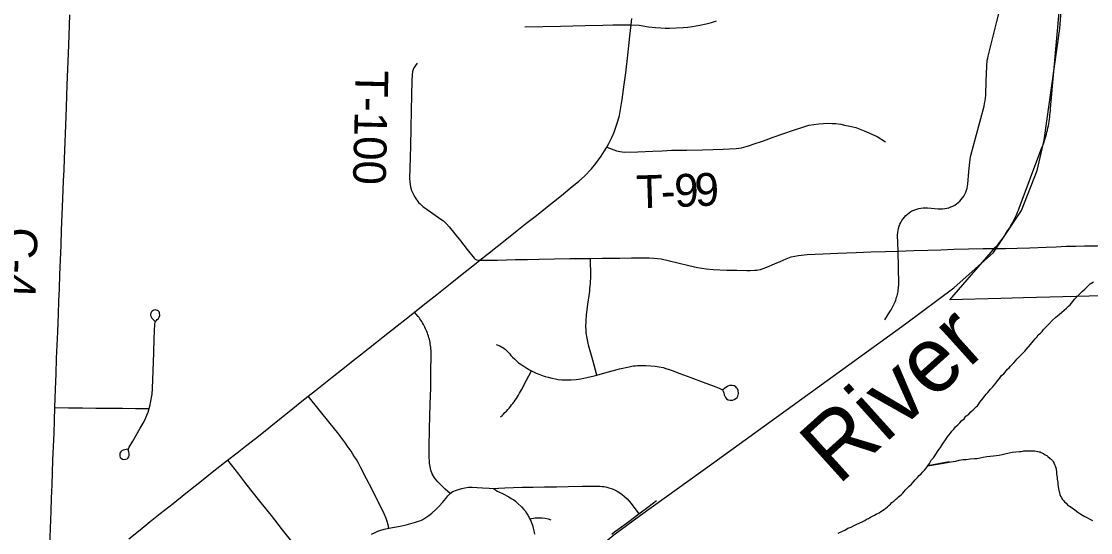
# Model space of a CAD drawing. Extents: x 103424 to 290657, y 38711 to 110967.
# Drawn here: x 133964 to 143819, y 91660 to 96372 of the extents above; entities that cross this region are included whole.
import ezdxf

# ---------------------------------------------------------------- set-up
doc = ezdxf.new("R2010")
doc.units = 0
for name, color, linetype in [('GM_X_Corporation', 7, 'Continuous'), ('GM_X_County_Road', 7, 'Continuous'), ('GM_X_County_Road_Text', 7, 'Continuous'), ('GM_X_Major_River', 7, 'Continuous'), ('GM_X_Major_River_Text', 7, 'Continuous'), ('GM_X_Minor_River', 7, 'Continuous'), ('GM_X_Rail_Line', 7, 'Continuous'), ('GM_X_Township_Road', 7, 'Continuous'), ('GM_X_Township_Road_Text', 7, 'Continuous')]:
    doc.layers.add(name, color=color, linetype=linetype)

msp = doc.modelspace()

# ---------------------------------------------------------------- linework, layer by layer
at = {"layer": 'GM_X_Corporation'}
msp.add_lwpolyline([(145135.5, 93872.2), (143199.9, 93823.5), (142990.7, 93818.2), (142521.7, 93806.3), (142943.1, 94290.2), (142970.1, 94321), (143003.1, 94365.9), (143020.5, 94390.6), (143037.3, 94415.7), (143053.7, 94441), (143069.6, 94466.6), (143085.2, 94492.5), (143100.3, 94518.6), (143114.7, 94545), (143129.5, 94576.7), (143137.6, 94595.2), (143145.4, 94613.8), (143152.7, 94632.5), (143159.8, 94651.4), (143361.2, 95186.5), (143373.3, 95216.1), (143380.4, 95234.9), (143387.2, 95253.9), (143393.5, 95273.1), (143399.5, 95292.3), (143405.3, 95311.6), (143410.9, 95331), (143415.9, 95350.5), (143420.7, 95370.2), (143425, 95389.8), (143429, 95409.6), (143432.8, 95429.4), (143436.1, 95449.3), (143439.1, 95469.2), (143441.9, 95489.2), (143444.2, 95509.2), (143446.2, 95529.3), (143447.7, 95549.4), (143449, 95569.5), (143589.8, 97142.1)], dxfattribs=at)
at = {"layer": 'GM_X_County_Road'}
for points in [[(134227.3, 91538.2), (134232.5, 91698.2), (134237.8, 91858.1), (134242.5, 91979.1), (134247.3, 92100), (134250.8, 92213.9), (134254.2, 92327.8), (134259.6, 92452.6), (134265.1, 92577.3), (134269.1, 92694.8), (134273.1, 92812.3), (134276.6, 92897.5), (134280.2, 92982.6), (134284.8, 93124), (134289.3, 93265.3), (134294.1, 93388.4), (134298.9, 93511.5), (134305.2, 93676.5), (134309.6, 93792.3), (134314.1, 93908.2), (134319.2, 94039.8), (134324.4, 94171.3), (134329.9, 94309.2), (134335.3, 94447), (134340.7, 94592.5), (134346.1, 94737.9), (134352.9, 94902.9), (134357.1, 95003.3), (134361.3, 95103.8), (134367.4, 95259.9), (134373.4, 95415.9), (134379, 95580.9), (134382.5, 95684.6), (134386, 95788.3), (134392.1, 95932), (134398.1, 96075.7), (134404.5, 96240.7), (134408.3, 96337), (134412, 96433.4)], [(134953.5, 91602.2), (135058.2, 91686.8), (135150.9, 91761.8), (135243.7, 91836.9), (135361.7, 91930.2), (135479.6, 92023.5), (135608.9, 92126.2), (135673.6, 92177.6), (135738.3, 92229), (135863.7, 92328.3), (135951.5, 92395), (136031, 92458.5), (136120.8, 92529.1), (136210.6, 92599.6), (136297.8, 92669.7), (136385, 92739.8), (136467.1, 92805.7), (136549.2, 92871.5), (136607.3, 92916.9), (136675.8, 92969.3), (136751.7, 93031.3), (136827.6, 93093.3), (136957.4, 93195.2), (137022.9, 93246.6), (137088.3, 93298), (137162.2, 93356.9), (137236, 93415.8), (137297.1, 93463.6), (137426.9, 93565.6), (137499.1, 93622.3), (137571.3, 93679), (137588.3, 93692.6), (137683, 93767.8), (137793.9, 93856), (137915.2, 93954.1), (138043.3, 94055.7), (138141.3, 94132.4), (138189.7, 94170.4), (138259.8, 94227.5), (138349.5, 94298.3), (138439.3, 94369), (138533.2, 94443.2), (138627.1, 94517.5), (138710.5, 94584.1), (138794, 94650.7), (138868.2, 94709.3), (138942.5, 94767.9), (139022.2, 94833.9), (139101.9, 94899.9), (139153.9, 94946.9), (139217.8, 95011.9), (139259.9, 95062.3), (139308.4, 95129.9), (139340, 95178.4), (139360.7, 95213.8), (139378.1, 95245.1), (139405.5, 95300.9), (139426.4, 95351.1), (139446.3, 95404.8), (139461.9, 95453), (139475.8, 95505.3), (139487.3, 95561.1), (139502, 95652.6), (139520.4, 95789.3), (139534.8, 95897.6), (139552.3, 96059.2), (139561.6, 96146.8), (139570.8, 96234.3), (139583.4, 96340.6), (139590.7, 96398.8)]]:
    msp.add_lwpolyline(points, dxfattribs=at)
at = {"layer": 'GM_X_Major_River'}
for points in [[(142128.7, 92068.5), (142142.6, 92084.9), (142166.4, 92107.6), (142182.2, 92126.1), (142202, 92146.6), (142221.8, 92167.2), (142239.6, 92185.7), (142255.5, 92202.2), (142271.3, 92220.6), (142287.2, 92237.1), (142303, 92255.5), (142318.7, 92276), (142334.5, 92298.5), (142350.1, 92327.1), (142371.9, 92349.7), (142383.7, 92368.1), (142393.5, 92384.4), (142405.3, 92402.8), (142415.1, 92417.2), (142424.9, 92433.5), (142434.8, 92445.8), (142444.6, 92460.1), (142454.4, 92474.4), (142487.8, 92523.5), (142499.6, 92541.9), (142513.4, 92558.3), (142527.2, 92576.8), (142541, 92595.2), (142556.8, 92613.7), (142574.6, 92634.2), (142594.4, 92654.8), (142612.3, 92673.3), (142632.1, 92693.8), (142652, 92710.3), (142669.7, 92734.9), (142695.6, 92751.5), (142713.4, 92772.1), (142735.3, 92790.6), (142751.1, 92807.1), (142765, 92819.5), (142774.9, 92829.7), (142788.7, 92848.2), (142798.5, 92862.5), (142812.3, 92880.9), (142830.1, 92901.4), (142843.9, 92919.9), (142857.7, 92938.3), (142871.6, 92950.7), (142883.4, 92967.1), (142897.3, 92981.4), (142913.1, 92999.9), (142928.9, 93020.4), (142944.7, 93038.9), (142960.5, 93059.4), (142978.2, 93081.9), (142997.9, 93108.5), (143017.8, 93125), (143031.7, 93139.4), (143041.6, 93151.7), (143053.4, 93166.1), (143067.3, 93180.5), (143081.2, 93192.9), (143095, 93209.3), (143110.8, 93225.7), (143126.7, 93242.2), (143142.5, 93260.6), (143160.3, 93279.1), (143182.1, 93301.8), (143198, 93318.2), (143213.9, 93332.6), (143223.7, 93346.9), (143265.2, 93394.2), (143277, 93410.5), (143290.8, 93429), (143306.7, 93445.4), (143322.5, 93461.9), (143336.2, 93484.3), (143356.2, 93498.8), (143372, 93515.3), (143385.8, 93531.7), (143407.6, 93556.3), (143435.3, 93585.1), (143465.1, 93613.9), (143496.8, 93644.8), (143528.6, 93671.7), (143552.5, 93692.3), (143576.3, 93710.9), (143596.2, 93729.4), (143616.1, 93746), (143629.9, 93760.3), (143641.8, 93774.7), (143653.6, 93791.1), (143669.4, 93811.6), (143687.2, 93830.1), (143705.1, 93846.6), (143722.9, 93865.1), (143742.7, 93885.6), (143764.6, 93904.2), (143788.4, 93926.8), (143814.1, 93953.6), (143846.1, 93972.3)], [(141490.5, 91655), (141504.5, 91661.3), (141518.5, 91667.6), (141532.5, 91673.9), (141546.5, 91680.3), (141560.5, 91686.6), (141580.4, 91701.1), (141612.5, 91711.7), (141634.5, 91724.3), (141658.5, 91734.8), (141720.6, 91764.2), (141738.6, 91772.6), (141754.5, 91783), (141770.5, 91791.4), (141790.5, 91803.8), (141808.5, 91812.2), (141826.5, 91822.7), (141842.5, 91829), (141854.4, 91837.3), (141868.5, 91843.6), (141884.4, 91854), (141900.4, 91864.4), (141916.3, 91874.8), (141930.2, 91887.2), (141946.2, 91897.6), (141960.1, 91909.9), (141974, 91922.3), (141985.8, 91936.7), (142005.8, 91951.2), (142021.6, 91965.6), (142035.5, 91978), (142049.4, 91990.3), (142061.4, 92000.7), (142075.3, 92013), (142087.2, 92025.4), (142101, 92039.7), (142112.9, 92054.1), (142128.7, 92068.5)]]:
    msp.add_lwpolyline(points, dxfattribs=at)
at = {"layer": 'GM_X_Minor_River'}
msp.add_lwpolyline([(142515.8, 92311.9), (142318.7, 92276), (142534, 92312.2), (142552.1, 92314.6), (142576.3, 92319), (142608.4, 92327.7), (142644.6, 92334.4), (142672.8, 92334.9), (142690.9, 92337.3), (142709.1, 92339.6), (142747.3, 92342.3), (142771.5, 92344.8), (142799.7, 92349.3), (142829.8, 92355.9), (142862, 92360.5), (142894.3, 92365.2), (142924.5, 92367.7), (142948.6, 92370.2), (142974.8, 92374.7), (143003, 92379.2), (143027.1, 92385.7), (143067.3, 92394.5), (143095.4, 92401.1), (143163.9, 92406.4), (143180, 92408.7), (143194.1, 92411), (143204.1, 92413.2), (143218.2, 92413.4), (143234.4, 92413.7), (143250.5, 92414), (143262.6, 92414.2), (143276.8, 92414.5), (143286.8, 92414.6), (143305, 92412.9), (143317.2, 92411.1), (143331.3, 92409.4), (143343.5, 92405.6), (143353.6, 92403.7), (143363.8, 92397.8), (143374, 92394), (143384.2, 92388.1), (143400.5, 92378.3), (143414.8, 92370.5), (143425, 92362.6), (143443.4, 92346.7), (143457.8, 92334.9), (143466, 92324.9), (143474.3, 92313), (143482.7, 92296.9), (143486.9, 92286.9), (143491.1, 92274.9), (143497.5, 92258.8), (143499.7, 92248.7), (143501.9, 92238.7), (143504.2, 92222.6), (143504.4, 92210.4), (143504.6, 92198.3), (143506.9, 92182.2), (143509.2, 92168.1), (143511.5, 92154), (143513.8, 92137.9), (143516.1, 92121.8), (143516.4, 92105.6), (143518.8, 92085.4), (143523.2, 92063.3), (143536.2, 92011), (143542.6, 91995), (143550.9, 91983), (143557.2, 91968.9), (143567.5, 91957), (143577.8, 91945.1), (143592.1, 91931.2), (143606.5, 91917.3), (143624.9, 91903.5), (143647.4, 91887.7), (143671.9, 91870), (143700.5, 91850.3), (143729.1, 91830.6), (143765.8, 91809), (143790.3, 91797.4), (143810.7, 91785.6), (143835.1, 91771.9)], dxfattribs=at)
at = {"layer": 'GM_X_Rail_Line'}
msp.add_lwpolyline([(133875.3, 84761), (134206.1, 85023.5), (134695.7, 85421.3), (135168.4, 85804.7), (135472.6, 86146.8), (135770.9, 86563.5), (136107.4, 87051.7), (138204.8, 90053), (139003.6, 91176.8), (139218.1, 91468.2), (139423.2, 91640.3), (139671.2, 91822), (140345.3, 92305.3), (142112.2, 93585.6), (142557.7, 93916.9), (142922.5, 94241.9), (143182.7, 94627.5), (143325.5, 94997.6), (143391, 95277.5), (143535.3, 96306.5), (143604.3, 97220.4), (143676.2, 97697.4)], dxfattribs=at)
at = {"layer": 'GM_X_Township_Road'}
for points in [[(139583.4, 96340.6), (139657.8, 96335.5), (139742.6, 96322.7), (139809.2, 96316.8), (139856.6, 96312.3), (139897.5, 96308.8), (139938, 96309.5), (140062.7, 96314.4), (140105.7, 96317.5), (140149.7, 96325.1), (140216.5, 96336.9), (140274.4, 96349), (140323.6, 96362.9), (140371.4, 96377)], [(142044.2, 94255.3), (142040.3, 94406.1), (142041.3, 94425.8), (142043.9, 94445.4), (142047.9, 94464.6), (142053.7, 94483.6), (142060.7, 94501.9), (142069, 94519.7), (142078.9, 94536.8), (142090.2, 94553.1), (142102.5, 94568.4), (142116.2, 94582.7), (142130.8, 94595.9), (142146.4, 94607.9), (142162.7, 94618.7), (142180.1, 94628.2), (142198.3, 94636.2), (142216.6, 94642.8), (142235.8, 94648), (142255.1, 94651.6), (142274.8, 94653.7), (142294.4, 94654.3), (142314.1, 94653.3), (142414.5, 94644.5), (142434.1, 94643.5), (142454, 94644.1), (142473.6, 94646.2), (142493, 94649.9), (142512.2, 94655.1), (142530.8, 94661.7), (142548.7, 94669.8), (142566.1, 94679.3), (142582.7, 94690.1), (142598.3, 94702.2), (142612.9, 94715.5), (142626.5, 94729.9), (142638.8, 94745.3), (142649.9, 94761.6), (142659.7, 94778.8), (142668.3, 94796.6), (142675.4, 94815.1), (142680.9, 94834.1), (142685, 94853.4), (142687.5, 94873), (142697.6, 94987.7), (142707.7, 95102.4), (142710.5, 95119.8), (142714.5, 95136.9), (142757.4, 95296.3), (142796.7, 95442.7), (142836.1, 95589.1), (142842.2, 95614.1), (142846.7, 95639.4), (142849.7, 95664.9), (142851.5, 95690.5), (142856.2, 95823.8), (142861, 95957.2), (142862.2, 95976.9), (142864, 95995), (142866.5, 96013.8), (142870.1, 96032.5), (142874.4, 96051), (142914.4, 96211.1), (142954.5, 96371.2), (142978, 96465.1)], [(138604.1, 96322.2), (138769.1, 96325.6), (138934.1, 96329), (139046.8, 96331.3), (139159.5, 96333.6), (139324.6, 96337.2), (139414.1, 96339.1), (139503.6, 96341), (139583.4, 96340.6)], [(137612.4, 95986), (137597.2, 95966.7), (137579.7, 95938.7), (137570.3, 95909.8), (137566.7, 95880.6), (137563.8, 95827.3), (137560.9, 95690.3), (137558, 95553.2), (137554, 95388.6), (137550, 95224), (137547.1, 95119.9), (137544.2, 95015.8), (137541.7, 94928.1), (137543.4, 94888.9), (137546.3, 94867.4), (137550.5, 94847.3), (137560.3, 94814.8), (137568.4, 94794), (137580.1, 94769.7), (137592.1, 94747.9), (137602.1, 94733), (137611.6, 94720.9), (137625.5, 94704.1), (137638.8, 94690.1), (137651.8, 94676.8), (137666.1, 94663.8), (137681.7, 94652.1), (137756.5, 94601), (137831.4, 94550), (137855.4, 94532.9), (137873.4, 94514.8), (137882.7, 94504.8), (137908, 94478.4), (138010.5, 94349), (138073.6, 94269.3), (138136.8, 94189.6), (138147.4, 94181.3), (138159.4, 94174.8), (138189.7, 94170.4)], [(139360.7, 95213.8), (139448.9, 95179.2), (139480.4, 95171.9), (139522.7, 95168.1), (139646, 95168.8), (139783.2, 95175.7), (139869.6, 95179.9), (139956, 95184.1), (140098.4, 95186.5), (140240.8, 95188.9), (140336, 95191.7), (140431.3, 95194.5), (140490.5, 95197.6), (140551.8, 95200.7), (140600, 95206.6), (140643.3, 95218), (140675.5, 95227.4), (140708.8, 95239.1), (140804, 95272), (140893.2, 95304), (140982.3, 95335.9), (141088.2, 95371.7), (141165.3, 95397.8), (141222.8, 95414.4), (141267.2, 95421), (141314.6, 95427.2), (141357.6, 95432.1), (141389.4, 95433.8), (141435.9, 95431.8), (141470.5, 95430.4), (141516.2, 95423.4), (141550.5, 95416.8), (141599.4, 95406.8), (141653.4, 95393.3), (141701.2, 95376.7), (141731.6, 95364.3), (141776, 95346.2), (141808.6, 95329.9), (141829.7, 95320.9), (141850.2, 95309.5), (141928.8, 95261)], [(142937.2, 94278.7), (143035.5, 94279.6), (143141.8, 94281.8), (143257.9, 94284.9), (143409, 94291.2), (143501.3, 94295.1), (143593.5, 94298.9), (143678.2, 94300.6), (143762.9, 94302.2), (143880.3, 94304.4), (143994.1, 94307.9), (144114.2, 94313.2), (144191.7, 94317.2), (144289.1, 94319), (144385.3, 94317.7), (144501.8, 94317.2), (144628.4, 94320.3), (144718.6, 94323.3), (144808.9, 94326.3), (144968.7, 94331.4), (145107.3, 94337.6), (145201.2, 94340.9), (145295, 94344.2)], [(138189.7, 94170.4), (138255.3, 94172), (138353.4, 94170.6), (138435.9, 94173.3), (138518.4, 94175.9), (138627.6, 94178.5), (138736.9, 94181.1), (138877.9, 94183.8), (139018.9, 94186.4), (139114.1, 94186.9), (139209.4, 94187.3), (139316, 94188.8), (139478.9, 94191.1), (139586.3, 94191.5), (139679.9, 94193.6), (139749.2, 94192.7), (139792.8, 94190.2), (139859.5, 94182.2), (140015.2, 94148.2), (140114.7, 94122.7), (140197, 94104.2), (140276.3, 94090.3), (140341.3, 94085.7), (140467.2, 94079.4), (140558.8, 94077.9), (140650.3, 94076.4), (140682.5, 94077), (140724.5, 94078.6), (140742.1, 94079.4), (140757.7, 94081.9), (140774.9, 94086.1), (140801.3, 94093.9), (140833.6, 94105.9), (140906.2, 94136.1), (140956.6, 94159.2), (141013.7, 94183.9), (141060.3, 94202.8), (141125.7, 94215.8), (141205.9, 94224.6), (141353.2, 94230.1), (141487.9, 94236.8), (141573.4, 94239.8), (141658.8, 94242.7), (141793.8, 94247.5), (141928.8, 94252.3), (142044.2, 94255.3), (142116.2, 94257.7), (142188.5, 94260.7), (142318.5, 94263.7), (142438.9, 94267.5), (142559.4, 94271.4), (142693.5, 94275), (142827.8, 94278.7), (142937.2, 94278.7)], [(141923.6, 93622.9), (141972.7, 93700.5), (141980, 93712.5), (141987.1, 93724.8), (141993.9, 93737.2), (142000.2, 93749.8), (142006.3, 93762.7), (142011.8, 93775.6), (142017.1, 93788.8), (142022.1, 93802), (142026.7, 93815.4), (142030.7, 93828.9), (142034.5, 93842.6), (142038, 93856.3), (142040.8, 93870.1), (142043.6, 93884), (142045.8, 93898), (142047.6, 93912.1), (142048.9, 93926.1), (142050.1, 93940.2), (142050.7, 93954.4), (142047.5, 94104.9), (142044.2, 94255.3)], [(139268.4, 93112.2), (139230.2, 93250.7), (139191.9, 93389.3), (139187.7, 93405.1), (139183.9, 93421), (139180.6, 93437), (139177.6, 93453.1), (139174.9, 93469.2), (139172.6, 93485.4), (139170.9, 93501.6), (139169.3, 93517.9), (139168.1, 93534.2), (139167.4, 93550.5), (139168.4, 93615.8), (139169.4, 93632.1), (139171.2, 93648.4), (139172.9, 93664.7), (139186.2, 93764.5), (139199.5, 93864.3), (139202.3, 93887), (139204.8, 93909.7), (139207, 93932.4), (139208.8, 93955.2), (139210.1, 93978.1), (139211.1, 94000.9), (139211.9, 94023.7), (139209.4, 94187.3)], [(135140.7, 92803.5), (135150.6, 92838.8), (135154.6, 92855.1), (135158.2, 92871.4), (135161.2, 92887.8), (135164, 92904.3), (135166.5, 92920.8), (135168.5, 92937.4), (135170, 92954), (135171.3, 92970.7), (135172.1, 92987.3), (135178.3, 93152.3), (135184.5, 93317.2), (135189.6, 93450.5), (135194.6, 93583.8), (135196.9, 93596.9), (135203.2, 93609), (135208.5, 93616), (135216.6, 93623.4), (135228.4, 93635.2), (135235.5, 93646.6), (135240.4, 93661.2), (135238.2, 93686.1), (135234.4, 93694.1), (135227.4, 93702.3), (135218.9, 93707.6), (135206.9, 93711.4), (135196.4, 93712.6), (135185.7, 93711.2), (135177.6, 93707.9), (135169.5, 93702.3), (135162.4, 93694.2), (135157, 93682.5), (135154.7, 93672.7), (135155.5, 93661.8), (135159.6, 93648.9), (135166, 93637.2), (135175.6, 93626.4), (135196.8, 93605.9)], [(137915.1, 92021.3), (137870.8, 92061.1), (137802.8, 92129.1), (137770.5, 92164.7), (137749.2, 92201.4), (137736.8, 92237), (137731, 92270.7), (137725.9, 92296.3), (137722.8, 92377.9), (137722.3, 92392.6), (137723.9, 92485), (137725.5, 92577.4), (137727.1, 92619.1), (137729.7, 92731.3), (137732.2, 92843.5), (137737.5, 92994.1), (137739.1, 93144.8), (137740.6, 93295.5), (137739.7, 93339.9), (137738.7, 93354.7), (137737.4, 93369.4), (137735.4, 93384.1), (137733.1, 93398.8), (137730.6, 93413.3), (137727.6, 93427.9), (137724.1, 93442.3), (137720.3, 93456.6), (137716.3, 93470.8), (137711.8, 93484.9), (137706.8, 93498.9), (137701.5, 93512.7), (137696, 93526.4), (137689.9, 93539.9), (137683.4, 93553.3), (137676.9, 93566.5), (137669.6, 93579.5), (137662.3, 93592.3), (137654.5, 93604.9), (137646.4, 93617.3), (137637.9, 93629.5), (137629.3, 93641.5), (137620, 93653.1), (137588.3, 93692.6)], [(138338.8, 93394.8), (138374.4, 93381.8), (138410.5, 93361.2), (138426.5, 93347.4), (138454.8, 93318.9), (138466.2, 93306.6), (138475.6, 93294.1), (138490, 93278.6), (138509.3, 93261.6), (138521.8, 93248.4), (138534.6, 93235.9), (138547.1, 93224.9), (138560.7, 93214.7), (138593.6, 93193.5), (138621.2, 93175.4), (138647.7, 93160.3), (138664.8, 93151.7), (138679.5, 93144), (138709.7, 93130.4), (138741.5, 93117.5), (138772.1, 93106.2), (138792.9, 93099.4), (138819.8, 93091.8), (138854.2, 93082.7), (138886.3, 93076.7), (138910.9, 93071.8), (138946.5, 93069.5), (138980.5, 93069.1), (139032.7, 93068.7), (139076.2, 93070.3), (139120.8, 93076.7), (139175.6, 93088.8), (139244.1, 93105.4), (139268.4, 93112.2), (139340.9, 93132.3), (139475.9, 93168.9), (139508.8, 93177.3), (139534.5, 93182.9), (139564.4, 93189.4), (139589.7, 93194.7), (139606, 93196.2), (139623.7, 93198.8), (139642.3, 93200), (139720.9, 93200.3), (139764.8, 93198.1), (139805.3, 93193.2), (139841.2, 93188.6), (139878.3, 93181.1), (139904.7, 93172.7), (139933.8, 93164.4), (139962.2, 93155), (140032.3, 93127.5), (140134.2, 93089.7), (140248.7, 93046.7), (140363.1, 93003.7), (140396.3, 92990.3), (140413.9, 92982.9), (140425.2, 92974.9), (140432.8, 92964.4), (140437.6, 92947.5), (140441.7, 92930), (140447.2, 92916.6), (140454.6, 92904.6), (140464.4, 92893.6), (140479.1, 92885.3), (140497.8, 92881.3), (140517, 92882.3), (140532.5, 92887.2), (140549.2, 92896.2), (140560, 92906.6), (140566.2, 92916.4), (140570.9, 92928.7), (140573.7, 92941.3), (140570.3, 92970.8), (140564.6, 92984.8), (140555.9, 92996.2), (140547.6, 93003.3), (140532.1, 93011.6), (140516.2, 93015.4), (140490.1, 93014.7), (140476.1, 93010.1), (140465.2, 93004.5), (140445.5, 92989.7), (140430.5, 92975.2)], [(138381.3, 92727.8), (138394.9, 92740.5), (138408.2, 92753.4), (138421.3, 92766.7), (138434.1, 92780.2), (138446.5, 92793.9), (138458.8, 92807.9), (138470.9, 92822.2), (138482.5, 92836.7), (138493.8, 92851.5), (138504.9, 92866.4), (138515.8, 92881.6), (138526.1, 92897), (138536.2, 92912.6), (138546, 92928.4), (138555.6, 92944.4), (138564.6, 92960.7), (138573.5, 92977.1), (138619.1, 93064.4), (138664.8, 93151.7)], [(137352.1, 91700.5), (137344.1, 91732.4), (137335.4, 91762.9), (137325, 91791), (137309.9, 91827.9), (137294.7, 91860.9), (137259, 91932.2), (137196.6, 92056.7), (137145.8, 92155.4), (137089.9, 92264.7), (137067.5, 92306.8), (137052, 92332.9), (137035.8, 92358.8), (137019.2, 92384.5), (137002.6, 92410), (136985.5, 92435.2), (136968.2, 92460.2), (136950.3, 92485.1), (136932.4, 92509.7), (136914.1, 92534.1), (136895.5, 92558.2), (136876.6, 92582.2), (136810.4, 92664.9), (136708.9, 92790.9), (136607.3, 92916.9)], [(134273.1, 92812.3), (134399.9, 92810.7), (134526.7, 92809.1), (134649.9, 92808.3), (134773.1, 92807.5), (134894.7, 92806.2), (135016.3, 92804.8), (135140.7, 92803.5)], [(134946.9, 92429.4), (134930.6, 92425.7), (134916.2, 92423.7), (134902.9, 92420), (134888.7, 92412.8), (134881.3, 92406.1), (134873.1, 92393.8), (134871.1, 92380.4), (134872.6, 92365), (134876.1, 92353.6), (134882.6, 92345.7), (134894.9, 92337.3), (134907.8, 92335.3), (134938, 92340.7), (134946.9, 92345.2), (134954.9, 92357.8), (134958.3, 92371.9), (134957.8, 92387.8), (134954.6, 92403.9), (134948.9, 92422.2), (134956.5, 92446.9), (134990.3, 92504.7), (135059.7, 92623.1), (135094.4, 92683.5), (135109.3, 92712.8), (135121.9, 92742.1), (135131.5, 92770.8), (135140.7, 92803.5)], [(135863.7, 92328.3), (135965.1, 92198), (136020.9, 92126.3), (136076.7, 92054.6), (136170.9, 91935.6), (136265, 91816.6), (136367.5, 91687.2), (136428.8, 91609.9), (136490.1, 91532.6), (136534.1, 91475.7)], [(137189.8, 91644.9), (137225.1, 91662.8), (137248.6, 91672.8), (137276.3, 91681.8), (137308.8, 91690.9), (137352.1, 91700.5), (137454.2, 91720), (137511, 91731.9), (137553.9, 91742.9), (137595.4, 91755.3), (137624, 91764.8), (137645.5, 91773), (137665.6, 91782.1), (137693.2, 91798.8), (137720.1, 91818.6), (137745.8, 91839.8), (137784.2, 91873.1), (137814.9, 91904.9), (137846.2, 91939.4), (137876, 91974.5), (137895.2, 91998.9), (137915.1, 92021.3), (137939.4, 92038), (137963.8, 92049.5), (137992, 92059.1), (138024.1, 92068.1), (138051, 92073.9), (138085.7, 92079), (138120.3, 92079.6), (138166.1, 92076.9), (138212.6, 92073.2), (138274.2, 92069.4), (138316.5, 92068.1), (138333.2, 92055.3), (138350.4, 92042.8), (138369.8, 92032.9), (138397.5, 92020.9), (138455.3, 91990.7), (138479.1, 91975.8), (138502.6, 91963.1), (138519.3, 91949.8), (138540.4, 91930.1), (138572.8, 91899.4), (138593.6, 91873.5), (138605.8, 91860.6), (138620.5, 91839.1), (138631.4, 91820.8), (138651.7, 91786.1), (138663.4, 91760.8), (138674.6, 91730.5), (138682.5, 91701.9), (138688.6, 91678), (138694.4, 91647.4)], [(138316.5, 92068.1), (138362, 92070), (138419.7, 92073.2), (138501.2, 92077.1), (138578.5, 92078.5), (138682.5, 92080), (138786.6, 92081.6), (138895.6, 92083.2), (139004.6, 92084.8), (139136.7, 92087.4), (139268.8, 92089.9), (139294.5, 92088.6), (139316.3, 92086.7), (139336.9, 92084.1), (139359.2, 92079.6), (139379.2, 92074.2), (139399.7, 92067.6), (139417.4, 92060.9), (139436.4, 92052.5), (139456.1, 92042.5), (139478.5, 92028.3), (139500.3, 92012.3), (139523.4, 91993.1), (139546, 91971.4), (139565.2, 91951.4), (139583.9, 91928.8), (139656.4, 91834.3)], [(139656.4, 91834.3), (139737.7, 91894.8), (139819, 91955.3)], [(138651.7, 91786.1), (138698.7, 91795.1), (138732.8, 91797.5), (138762.8, 91796.6), (138792.7, 91792.8), (138819.2, 91787.1), (138843.4, 91779)], [(139405.6, 91646.3), (139431.7, 91667.1), (139460.7, 91689), (139564.2, 91761.4), (139656.4, 91834.3)]]:
    msp.add_lwpolyline(points, dxfattribs=at)

# ---------------------------------------------------------------- texts
at = {"layer": 'GM_X_County_Road_Text'}
msp.add_text('C-4', height=301.87, rotation=268.16641, dxfattribs=at).set_placement((133813.2, 94477))
at = {"layer": 'GM_X_Major_River_Text'}
msp.add_text('River', height=604.19, rotation=42.01408, dxfattribs=at).set_placement((141491.3, 92089.3))
at = {"layer": 'GM_X_Township_Road_Text'}
for s, height, rotation, p in [('T-100', 301.87, 268.59705, (137045.7, 95923.3)), ('T', 301.9, 1.86032, (139636.3, 94649.3)), ('9', 301.9, 1.99064, (139986.7, 94660.8)), ('9', 301.9, 2.56593, (140175.8, 94667.4)), ('-', 301.9, 1.88635, (139862.2, 94656.7))]:
    msp.add_text(s, height=height, rotation=rotation, dxfattribs=at).set_placement(p)

doc.saveas('drawing.dxf')
